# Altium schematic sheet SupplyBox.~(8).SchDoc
size B; SheetNumber: 1; SheetTotal: 1
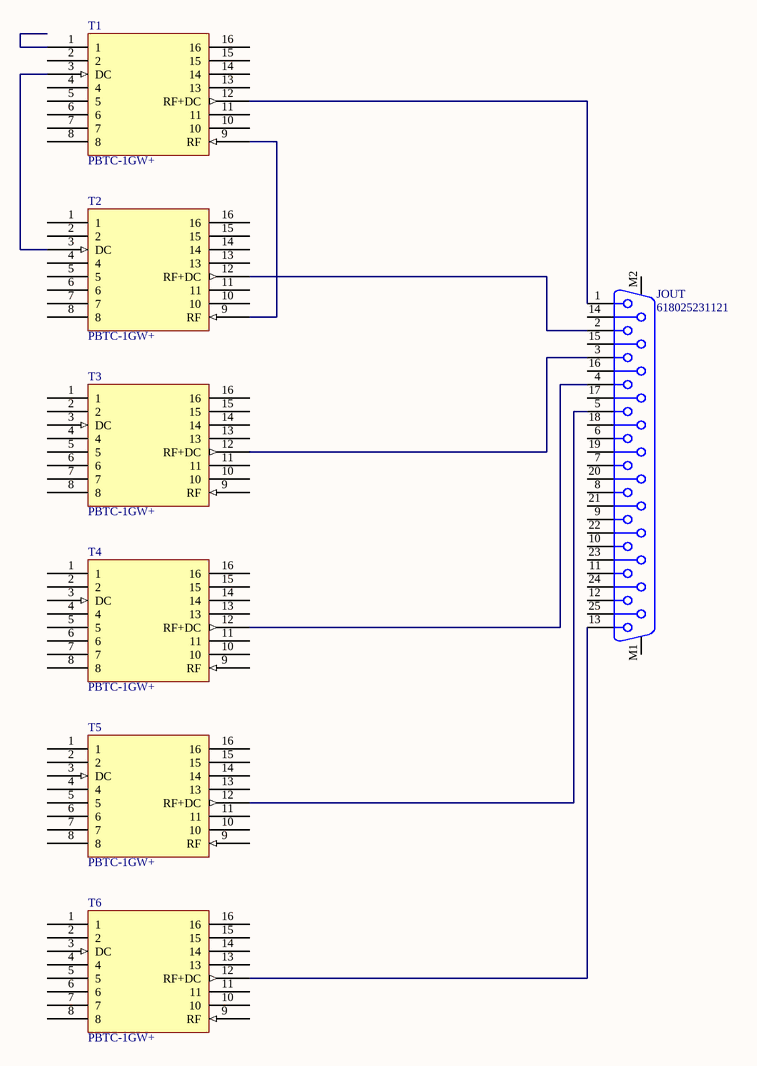
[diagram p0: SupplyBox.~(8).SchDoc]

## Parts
JOUT  618025231121  [618025231121]
T1  PBTC-1GW+  [PBTC-1GW+]
T2  PBTC-1GW+  [PBTC-1GW+]
T3  PBTC-1GW+  [PBTC-1GW+]
T4  PBTC-1GW+  [PBTC-1GW+]
T5  PBTC-1GW+  [PBTC-1GW+]
T6  PBTC-1GW+  [PBTC-1GW+]

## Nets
NetJOUT_1: JOUT.1 T1.12(RF+DC)
NetJOUT_2: JOUT.2 T2.12(RF+DC)
NetJOUT_3: JOUT.3 T3.12(RF+DC)
NetJOUT_4: JOUT.4 T4.12(RF+DC)
NetJOUT_5: JOUT.5 T5.12(RF+DC)
NetJOUT_13: JOUT.13 T6.12(RF+DC)
NetT1_3: T1.3(DC) T2.3(DC)
NetT1_9: T1.9(RF) T2.9(RF)

Not connected (* = marked no-connect by the designer): JOUT 6 7 8 9 10 11 12 14 15 16 17 18 19 20 21 22 23 24 25 M1 M2; T1 1 2 4 5 6 7 8 10 11 13 14 15 16; T2 1 2 4 5 6 7 8 10 11 13 14 15 16; T3 1 2 3(DC) 4 5 6 7 8 9(RF) 10 11 13 14 15 16; T4 1 2 3(DC) 4 5 6 7 8 9(RF) 10 11 13 14 15 16; T5 1 2 3(DC) 4 5 6 7 8 9(RF) 10 11 13 14 15 16; T6 1 2 3(DC) 4 5 6 7 8 9(RF) 10 11 13 14 15 16

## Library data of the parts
JOUT = CMP-1502-00202-2: NexarPartId: 18818207; Pitch: 2.77mm; Operating Supply Voltage: 125V; Gender: Female; Insulation Resistance: 5GΩ; Contact Resistance: 30mΩ; Current Rating: 3A; Number of Contacts: 25
T1-T6 = CMP-00025-00003-1: Monitor TEE DC Block, 0.1MHz Min, 1000MHz Max, 1dB Insertion Loss-Max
